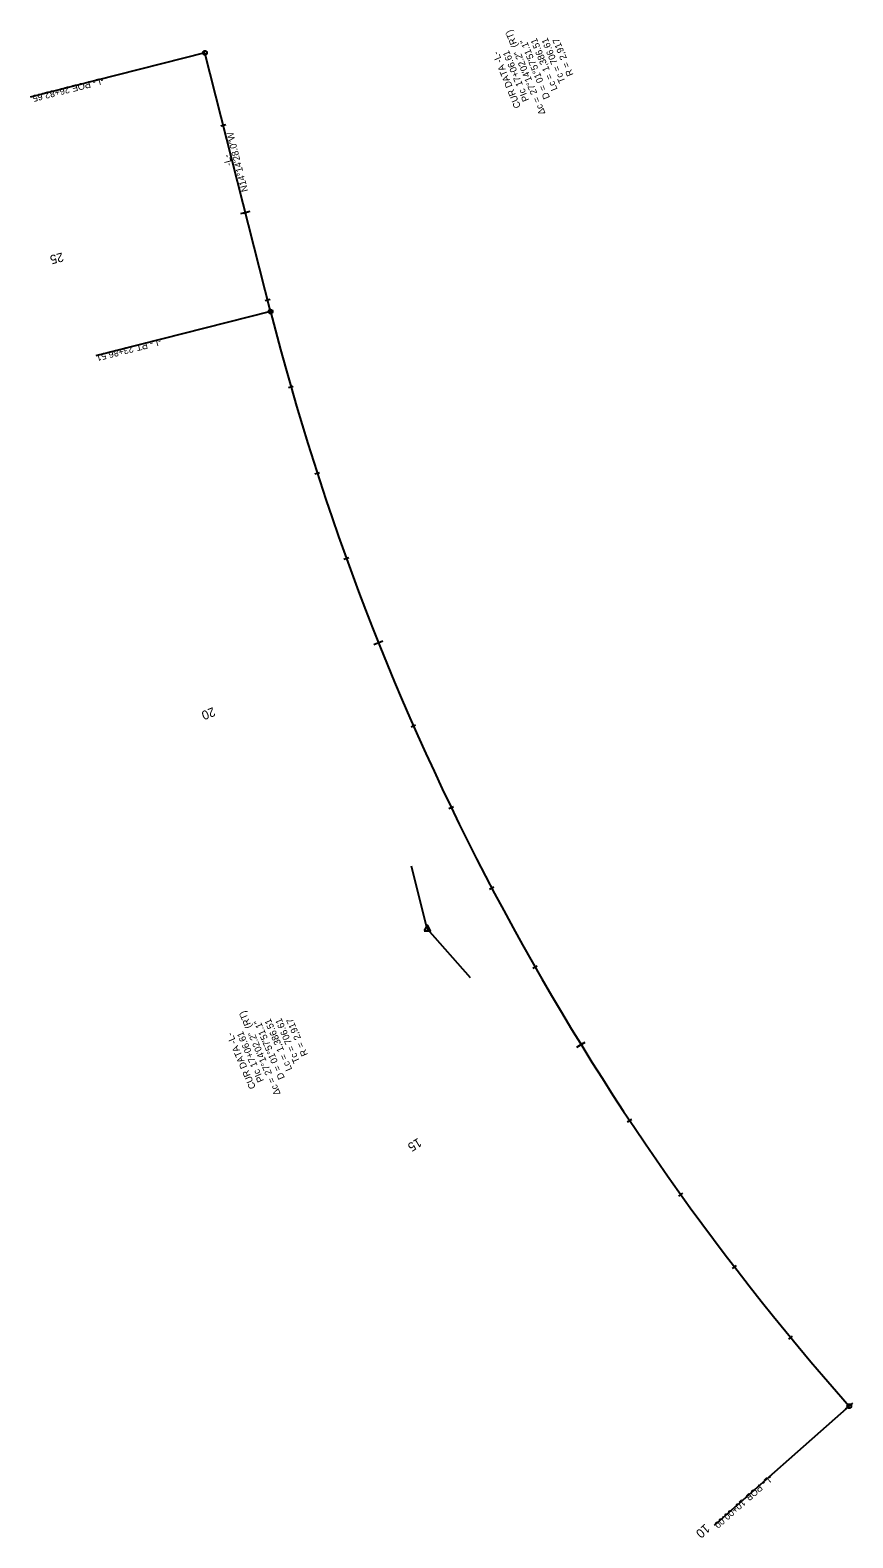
# Model space of a CAD drawing. Extents: x 1551430 to 1552343, y 809767 to 811440.
import ezdxf

# ---------------------------------------------------------------- set-up
doc = ezdxf.new("R2010")
doc.units = 0
for name, color, linetype in [('Default', 7, 'Continuous'), ('P_HYD_Contour_Major', 7, 'Continuous'), ('P_HYD_Contour_Minor', 7, 'Continuous'), ('P_HYD_TC_Ditch_DDE', 7, 'Continuous'), ('P_HYD_TC_Surface_Grass', 7, 'Continuous'), ('P_HYD_TL_Ditch_Base', 7, 'Continuous'), ('P_HYD_TL_Ditch_Boundary', 7, 'Continuous'), ('P_HYD_TL_Ditch_Mid', 7, 'Continuous'), ('P_HYD_TL_Slope_Stake_Fill', 7, 'Continuous')]:
    doc.layers.add(name, color=color, linetype=linetype)

msp = doc.modelspace()

# ---------------------------------------------------------------- linework, layer by layer
at = {"layer": 'Default'}
for q in [(1551852.9, 810512.4), (1551918.3, 810388.7), (1551870.6, 810442.7)]:
    msp.add_line((1551870.6, 810442.7), q, dxfattribs=at)
msp.add_lwpolyline([(1551867, 810440.7), (1551874.2, 810440.4), (1551870.8, 810446.8)], close=True, dxfattribs=at)
at = {"layer": 'P_HYD_TC_Ditch_DDE'}
for p, q in [((1551624, 811414.6), (1551430.1, 811365.4)), ((1551696.8, 811127.6), (1551503, 811078.4)), ((1552338.6, 809913.2), (1552188.8, 809780.8))]:
    msp.add_line(p, q, dxfattribs=at)
for centre in [(1551624, 811414.6), (1551696.8, 811127.6), (1552338.6, 809913.2)]:
    msp.add_circle(centre, 2.25, dxfattribs=at)
at = {"layer": 'P_HYD_TL_Ditch_Base'}
for centre in [(1551696.8, 811127.6), (1551945.2, 810482.1)]:
    msp.add_circle(centre, 0.05, dxfattribs=at)
at = {"layer": 'P_HYD_TL_Ditch_Boundary'}
for p, q in [((1551641.6, 811333.8), (1551647, 811335.2)), ((1551666.2, 811236.9), (1551671.6, 811238.2)), ((1551690.8, 811139.9), (1551696.2, 811141.3)), ((1551716.7, 811043.3), (1551722, 811044.8)), ((1551745.8, 810947.5), (1551751.1, 810949.2)), ((1551778.2, 810852.8), (1551783.4, 810854.7)), ((1551852.7, 810667), (1551857.7, 810669.2)), ((1551894.6, 810576.1), (1551899.6, 810578.5)), ((1551939.6, 810486.8), (1551944.5, 810489.3)), ((1551987.7, 810399), (1551992.5, 810401.7)), ((1552038.8, 810312.9), (1552043.5, 810315.8)), ((1552092.8, 810228.6), (1552097.4, 810231.7)), ((1552149.6, 810146.2), (1552154.1, 810149.4)), ((1552209.2, 810065.8), (1552213.6, 810069.2)), ((1552271.6, 809987.5), (1552275.8, 809991))]:
    msp.add_line(p, q, dxfattribs=at)
at = {"layer": 'P_HYD_TL_Ditch_Mid'}
msp.add_line((1551696.8, 811127.6), (1551624, 811414.6), dxfattribs=at)
msp.add_arc((1554524.2, 811845.1), 2917, 194.2411, 221.4751, dxfattribs=at)
at = {"layer": 'P_HYD_TL_Slope_Stake_Fill'}
for p, q in [((1551663.7, 811236.2), (1551674, 811238.8)), ((1551811.4, 810758.3), (1551821.3, 810762.3)), ((1552036.6, 810311.5), (1552045.6, 810317.1)), ((1552334.6, 809909.7), (1552342.6, 809916.7))]:
    msp.add_line(p, q, dxfattribs=at)

# ---------------------------------------------------------------- texts
at = {"layer": 'P_HYD_Contour_Major'}
for s, p in [('N14°14\'28.0"W', (1551671.9, 811261.4)), ('L', (1551653.2, 811293.5)), ('-', (1551651.7, 811299.1)), ('-', (1551654, 811290.1))]:
    msp.add_text(s, height=7.5, rotation=104.2411, dxfattribs=at).set_placement(p)
at = {"layer": 'P_HYD_Contour_Minor'}
for s, rotation, p in [('25', 194.2411, (1551465.7, 811193.2)), ('20', 201.833, (1551633, 810688.9)), ('15', 211.654, (1551860.5, 810211.2)), ('10', 221.4751, (1552178.7, 809783.2))]:
    msp.add_text(s, height=10, rotation=rotation, dxfattribs=at).set_placement(p)
at = {"layer": 'P_HYD_TC_Ditch_DDE'}
for s, height, rotation, p in [('-L- POE 26+82.65', 7.5, 194.2411, (1551510.7, 811387.3)), ('26+82.65', 0.0125, 194.2411, (1551430.2, 811365.4)), ('- ', 0.0125, 194.2411, (1551430.2, 811365.4)), ('POE', 0.0125, 194.2411, (1551430.2, 811365.4)), ('-', 0.0125, 194.2411, (1551430.3, 811365.4)), ('L', 0.0125, 194.2411, (1551430.3, 811365.4)), ('PT', 7.5, 194.2411, (1551559.4, 811094)), ('- ', 7.5, 194.2411, (1551565.6, 811095.6)), ('L', 7.5, 194.2411, (1551571.2, 811097)), ('-', 7.5, 194.2411, (1551574.6, 811097.9)), ('23+86.51', 7.5, 194.2411, (1551543.6, 811090)), ('POB', 7.5, 221.4751, (1552238.5, 809827)), ('- ', 7.5, 221.4751, (1552243.3, 809831.3)), ('L', 7.5, 221.4751, (1552247.6, 809835.1)), ('-', 7.5, 221.4751, (1552250.2, 809837.4)), ('10+00.00', 7.5, 221.4751, (1552219.7, 809810.5))]:
    msp.add_text(s, height=height, rotation=rotation, dxfattribs=at).set_placement(p)
at = {"layer": 'P_HYD_TC_Surface_Grass'}
for s, rotation, p in [(' (RT)', 112.1864, (1551972.4, 811419.6)), ('01°57\'51.1"', 112.1864, (1551999.5, 811383)), ('1,386.51', 112.1864, (1552006.5, 811395.5)), ('706.61', 112.1864, (1552015.4, 811403.5)), ('2,917', 112.1864, (1552025.6, 811408.5)), ('L', 112.1864, (1551952.7, 811408.5)), ('-', 112.1864, (1551950.5, 811413.9)), ('17+06.61', 112.1864, (1551976.8, 811379)), ('27°14\'02.2"', 112.1864, (1551992.7, 811370)), ('CUR DATA -', 112.1864, (1551974.5, 811354.9)), ('Tc = ', 112.1864, (1552023.9, 811382.8)), ('R = ', 112.1864, (1552032.9, 811390.4)), ('D = ', 112.1864, (1552006.8, 811365)), ('Lc = ', 112.1864, (1552015.2, 811374.2)), ('PIc ', 112.1864, (1551983.7, 811362.3)), ('Δc = ', 112.1864, (1552001.8, 811347.6)), (' (RT)', 113.1736, (1551677.4, 810331.5)), ('01°57\'51.1"', 113.1736, (1551705, 810295.4)), ('1,386.51', 113.1736, (1551711.9, 810308)), ('706.61', 113.1736, (1551720.6, 810316.2)), ('2,917', 113.1736, (1551730.7, 810321.3)), ('L', 113.1736, (1551657.8, 810320)), ('-', 113.1736, (1551655.5, 810325.4)), ('17+06.61', 113.1736, (1551682.5, 810291)), ('27°14\'02.2"', 113.1736, (1551698.5, 810282.2)), ('CUR DATA -', 113.1736, (1551680.6, 810266.9)), ('Tc = ', 113.1736, (1551729.4, 810295.6)), ('R = ', 113.1736, (1551738.4, 810303.3)), ('D = ', 113.1736, (1551712.7, 810277.5)), ('Lc = ', 113.1736, (1551720.9, 810286.9)), ('PIc ', 113.1736, (1551689.6, 810274.4)), ('Δc = ', 113.1736, (1551708, 810260))]:
    msp.add_text(s, height=7.5, rotation=rotation, dxfattribs=at).set_placement(p)

doc.saveas('drawing.dxf')
